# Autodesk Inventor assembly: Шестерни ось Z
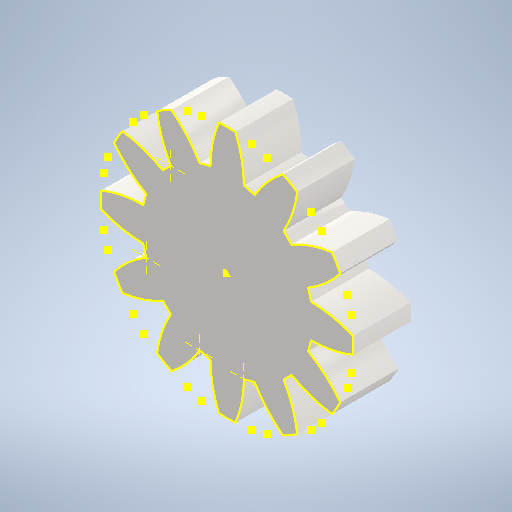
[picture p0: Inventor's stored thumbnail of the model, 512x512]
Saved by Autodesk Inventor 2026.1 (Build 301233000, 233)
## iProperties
Created: 2026-01
Part Number: Шестерни ось Z
Document SubType Name: Assembly
Designer: Yury Melnikov
Author: Yury Melnikov
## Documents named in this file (2)
- C:\Users\user\Documents\Проекты\ВсОШ_РОБО\Робот V2\Шестерни ось Z.iam
- C:\Users\user\Documents\Проекты\ВсОШ_РОБО\Робот V2\Шестерни ось Z\Мастер проектирования\Цилиндрическое зубчатое зацепление1.iam
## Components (1 placed, 1 different names)
1. Цилиндрическое зубчатое зацепление:1 [sub-assembly]
